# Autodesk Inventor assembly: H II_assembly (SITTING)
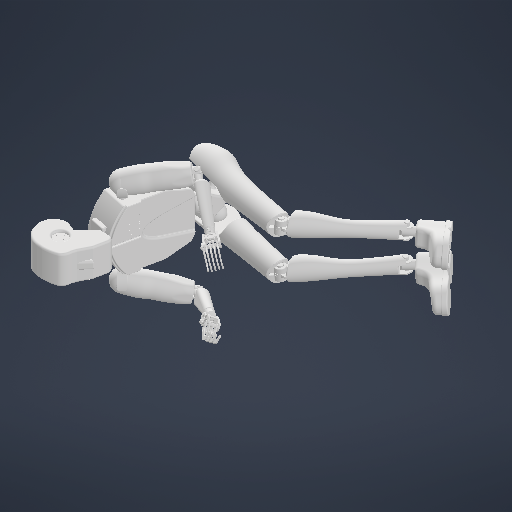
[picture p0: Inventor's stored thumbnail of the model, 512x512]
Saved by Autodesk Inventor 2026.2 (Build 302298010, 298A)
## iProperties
Company: none
Created: 2016-10
Part Number: H II_assembly (SITTING)
Description: CATIA V5 STEP Exchange
Document SubType Name: Assembly
Designer: cpEwe
Authority: none
Title: C:\Users\TANMAYA\Desktop\GRABCAD\H II_assembly (SITTING).stp
Author: none
Sending System: CATIA V5 STEP AP203
Preprocessor: CATIA Version 5 Release 20 SP 1 (IN-10)
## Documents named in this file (24)
- C:\Users\cpEwe\Documents\dynimics\star climber milestone 2\cad files\imports\human\H II_assembly (SITTING).iam
- C:\Users\cpEwe\Downloads\H II_assembly (SITTING)\H II_assembly (SITTING)\HEAD.ipt
- C:\Users\cpEwe\Downloads\H II_assembly (SITTING)\H II_assembly (SITTING)\NECK.ipt
- C:\Users\cpEwe\Downloads\H II_assembly (SITTING)\H II_assembly (SITTING)\SPINAL CORD.ipt
- C:\Users\cpEwe\Downloads\H II_assembly (SITTING)\H II_assembly (SITTING)\TORSO.ipt
- C:\Users\cpEwe\Downloads\H II_assembly (SITTING)\H II_assembly (SITTING)\HIP.ipt
- C:\Users\cpEwe\Downloads\H II_assembly (SITTING)\H II_assembly (SITTING)\LLU.ipt
- C:\Users\cpEwe\Downloads\H II_assembly (SITTING)\H II_assembly (SITTING)\RLU.ipt
- C:\Users\cpEwe\Downloads\H II_assembly (SITTING)\H II_assembly (SITTING)\LEFT LEG-L.ipt
- C:\Users\cpEwe\Downloads\H II_assembly (SITTING)\H II_assembly (SITTING)\RIGHT LEG-L.ipt
- C:\Users\cpEwe\Downloads\H II_assembly (SITTING)\H II_assembly (SITTING)\LEFT ANKLE.ipt
- C:\Users\cpEwe\Downloads\H II_assembly (SITTING)\H II_assembly (SITTING)\RIGHT ANKLE.ipt
- C:\Users\cpEwe\Downloads\H II_assembly (SITTING)\H II_assembly (SITTING)\LEFT SHOE.ipt
- C:\Users\cpEwe\Downloads\H II_assembly (SITTING)\H II_assembly (SITTING)\RIGHT SHOE.ipt
- C:\Users\cpEwe\Downloads\H II_assembly (SITTING)\H II_assembly (SITTING)\SHOULDER-L.ipt
- C:\Users\cpEwe\Downloads\H II_assembly (SITTING)\H II_assembly (SITTING)\SHOULDER-R.ipt
- C:\Users\cpEwe\Downloads\H II_assembly (SITTING)\H II_assembly (SITTING)\LH-U.ipt
- C:\Users\cpEwe\Downloads\H II_assembly (SITTING)\H II_assembly (SITTING)\RH-U.ipt
- C:\Users\cpEwe\Downloads\H II_assembly (SITTING)\H II_assembly (SITTING)\ELBOW-L.ipt
- C:\Users\cpEwe\Downloads\H II_assembly (SITTING)\H II_assembly (SITTING)\ELBOW-R.ipt
- C:\Users\cpEwe\Downloads\H II_assembly (SITTING)\H II_assembly (SITTING)\LEFT ARM-L.ipt
- C:\Users\cpEwe\Downloads\H II_assembly (SITTING)\H II_assembly (SITTING)\RIGHT ARM-L.ipt
- C:\Users\cpEwe\Downloads\H II_assembly (SITTING)\H II_assembly (SITTING)\LEFT HAND ASSEMBLY.iam
- C:\Users\cpEwe\Downloads\H II_assembly (SITTING)\H II_assembly (SITTING)\RIGHT HAND ASSEMBLY.iam
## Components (23 placed, 23 different names)
1. HEAD.1
2. NECK.1
3. SPINAL CORD.1
4. TORSO.1
5. HIP.1
6. LLU.1
7. RLU.1
8. LEFT LEG-L.1
9. RIGHT LEG-L.1
10. LEFT ANKLE.1
11. RIGHT ANKLE.1
12. LEFT SHOE.1
13. RIGHT SHOE.1
14. SHOULDER-L.1
15. SHOULDER-R.1
16. LH-U.1
17. RH-U.1
18. ELBOW-L.1
19. ELBOW-R.1
20. LEFT ARM-L.1
21. RIGHT ARM-L.1
22. LEFT HAND ASSEMBLY.1 [sub-assembly]
23. RIGHT HAND ASSEMBLY.1 [sub-assembly]
